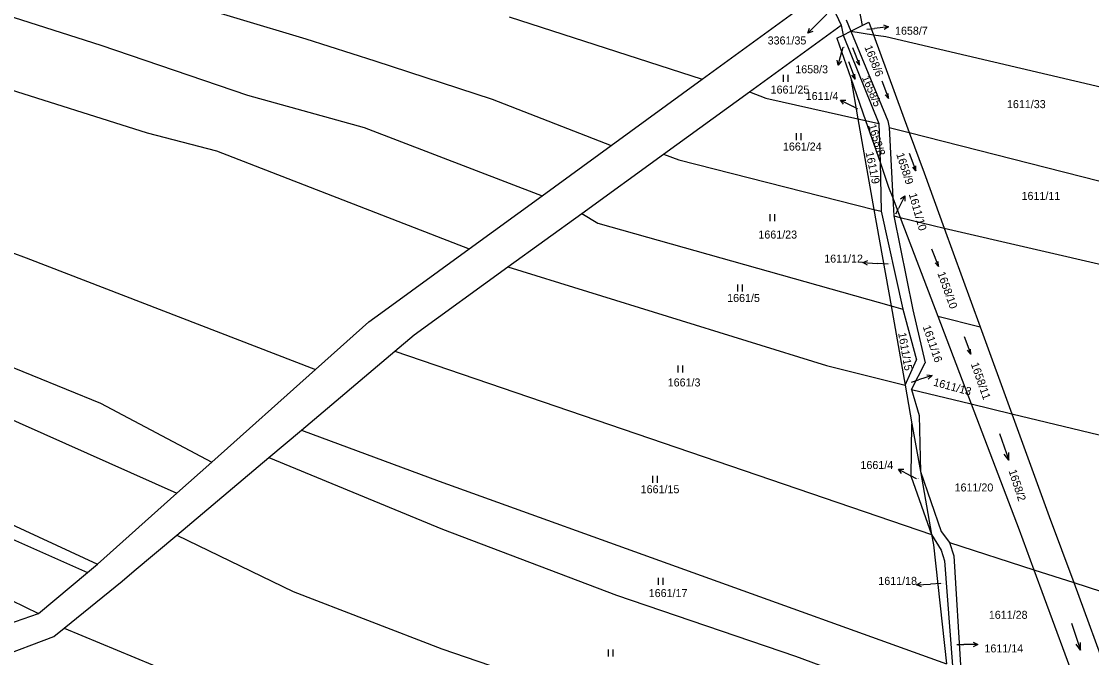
# Model space of a CAD drawing. Extents: x -763205 to -760228, y -1155311 to -1152844.
# Drawn here: x -761366.2 to -761138.9, y -1155010.6 to -1154875.5 of the extents above; entities that cross this region are included whole.
import ezdxf

# ---------------------------------------------------------------- set-up
doc = ezdxf.new("R2010")
doc.units = 0
for name, color, linetype in [('Vrstva 1', 7, 'Continuous'), ('Vrstva 16', 7, 'Continuous'), ('Vrstva 18', 7, 'Continuous'), ('Vrstva 25', 7, 'Continuous'), ('Vrstva 6', 7, 'Continuous')]:
    doc.layers.add(name, color=color, linetype=linetype)

msp = doc.modelspace()

# ---------------------------------------------------------------- linework, layer by layer
at = {"layer": 'Vrstva 1'}
for p, q in [((-761195.65, -1154868.82), (-761192.1, -1154876.29)), ((-761221.63, -1154887.74), (-761201.41, -1154873.02)), ((-761188.31, -1154873.02), (-761187.68, -1154876.37)), ((-761211.62, -1154890.45), (-761192.1, -1154876.29)), ((-761192.1, -1154876.29), (-761191.73, -1154878.38)), ((-761191.73, -1154878.38), (-761190.05, -1154877.55)), ((-761190.05, -1154877.55), (-761187.68, -1154876.37)), ((-761187.68, -1154876.37), (-761186.24, -1154875.66)), ((-761186.24, -1154875.66), (-761185.28, -1154878.29)), ((-761193.07, -1154879.04), (-761191.73, -1154878.38)), ((-761193.07, -1154879.04), (-761190.11, -1154887.54)), ((-761185.28, -1154878.29), (-761177.67, -1154899.07)), ((-761241, -1154901.84), (-761221.63, -1154887.74)), ((-761190.11, -1154887.54), (-761188.58, -1154896.17)), ((-761190.11, -1154887.54), (-761186.97, -1154896.53)), ((-761229.89, -1154903.7), (-761211.62, -1154890.45)), ((-761188.58, -1154896.17), (-761185.17, -1154915.39)), ((-761186.97, -1154896.53), (-761183.88, -1154905.38)), ((-761177.67, -1154899.07), (-761174.53, -1154907.64)), ((-761255.66, -1154912.52), (-761241, -1154901.84)), ((-761247.22, -1154916.27), (-761229.89, -1154903.7)), ((-761183.88, -1154905.38), (-761182.05, -1154910.64)), ((-761174.53, -1154907.64), (-761170.25, -1154919.38)), ((-761182.05, -1154910.64), (-761181.17, -1154912.96)), ((-761271.12, -1154923.77), (-761255.66, -1154912.52)), ((-761181.17, -1154912.96), (-761179.59, -1154917.1)), ((-761262.89, -1154927.63), (-761247.22, -1154916.27)), ((-761185.17, -1154915.39), (-761181.53, -1154935.91)), ((-761179.59, -1154917.1), (-761171.61, -1154938.06)), ((-761170.25, -1154919.38), (-761162.6, -1154940.36)), ((-761289.89, -1154937.43), (-761271.12, -1154923.77)), ((-761282.79, -1154942.07), (-761262.89, -1154927.63)), ((-761181.53, -1154935.91), (-761178.55, -1154952.76)), ((-761292.41, -1154939.27), (-761289.89, -1154937.43)), ((-761171.61, -1154938.06), (-761164.52, -1154956.7)), ((-761301.81, -1154947.66), (-761292.41, -1154939.27)), ((-761162.6, -1154940.36), (-761155.88, -1154958.78)), ((-761286.9, -1154945.53), (-761282.79, -1154942.07)), ((-761306.76, -1154962.27), (-761286.9, -1154945.53)), ((-761303.78, -1154949.42), (-761301.81, -1154947.66)), ((-761325.77, -1154969.06), (-761303.78, -1154949.42)), ((-761178.55, -1154952.76), (-761177.1, -1154960.95)), ((-761164.52, -1154956.7), (-761154.35, -1154983.45)), ((-761155.88, -1154958.78), (-761147.93, -1154980.59)), ((-761177.1, -1154960.95), (-761175.3, -1154971.09)), ((-761313.66, -1154968.08), (-761306.76, -1154962.27)), ((-761333.24, -1154984.59), (-761313.66, -1154968.08)), ((-761333.18, -1154975.68), (-761325.77, -1154969.06)), ((-761175.3, -1154971.09), (-761172.94, -1154984.41)), ((-761387.81, -1154973.33), (-761350.06, -1154990.75)), ((-761350.06, -1154990.75), (-761333.18, -1154975.68)), ((-761147.93, -1154980.59), (-761142.75, -1154994.66)), ((-761342.25, -1154992.18), (-761333.24, -1154984.59)), ((-761172.94, -1154984.41), (-761172.54, -1154986.65)), ((-761154.35, -1154983.45), (-761151.21, -1154991.93)), ((-761172.54, -1154986.65), (-761169.79, -1155011.88)), ((-761352.18, -1154992.53), (-761350.06, -1154990.75)), ((-761362.61, -1155001.24), (-761352.18, -1154992.53)), ((-761344.85, -1154994.37), (-761342.25, -1154992.18)), ((-761151.21, -1154991.93), (-761139.81, -1155022.71)), ((-761357.13, -1155004.33), (-761344.85, -1154994.37)), ((-761142.75, -1154994.66), (-761131.35, -1155025.67)), ((-761370.7, -1155004.05), (-761362.61, -1155001.24)), ((-761359.34, -1155006.12), (-761357.13, -1155004.33)), ((-761380.91, -1155014.27), (-761359.34, -1155006.12))]:
    msp.add_line(p, q, dxfattribs=at)
at = {"layer": 'Vrstva 16'}
for p, q in [((-761193.39, -1154872.07), (-761197.08, -1154875.83)), ((-761199.178, -1154877.974), (-761197.08, -1154875.83)), ((-761186.67, -1154877.14), (-761185.06, -1154876.95)), ((-761182.08, -1154876.601), (-761185.06, -1154876.95)), ((-761192.774, -1154884.791), (-761192.01, -1154881.89)), ((-761191.76, -1154880.95), (-761192.01, -1154881.89)), ((-761192.263, -1154892.169), (-761189.61, -1154893.57)), ((-761188.62, -1154894.09), (-761189.61, -1154893.57)), ((-761178.6, -1154912.506), (-761179.94, -1154915.19)), ((-761180.52, -1154916.35), (-761179.94, -1154915.19)), ((-761187.505, -1154926.701), (-761184.51, -1154926.88)), ((-761182.16, -1154927.02), (-761184.51, -1154926.88)), ((-761177.17, -1154952.11), (-761175.68, -1154951.62)), ((-761172.829, -1154950.686), (-761175.68, -1154951.62)), ((-761179.937, -1154970.532), (-761177.31, -1154971.98)), ((-761176.13, -1154972.63), (-761177.31, -1154971.98)), ((-761176.125, -1154995.145), (-761173.13, -1154994.97)), ((-761170.97, -1154994.84), (-761173.13, -1154994.97)), ((-761167.53, -1155007.78), (-761166.09, -1155007.78)), ((-761163.09, -1155007.781), (-761166.09, -1155007.78))]:
    msp.add_line(p, q, dxfattribs=at)
for points in [[(-761198.121, -1154877.609), (-761199.178, -1154877.974), (-761198.836, -1154876.91)], [(-761183.132, -1154876.221), (-761182.08, -1154876.601), (-761183.015, -1154877.214)], [(-761192.036, -1154883.951), (-761192.774, -1154884.791), (-761193.003, -1154883.697)], [(-761191.612, -1154893.078), (-761192.263, -1154892.169), (-761191.145, -1154892.194)], [(-761179.494, -1154913.177), (-761178.6, -1154912.506), (-761178.599, -1154913.624)], [(-761186.536, -1154927.26), (-761187.505, -1154926.701), (-761186.477, -1154926.261)], [(-761173.935, -1154950.522), (-761172.829, -1154950.686), (-761173.624, -1154951.472)], [(-761179.303, -1154971.452), (-761179.937, -1154970.532), (-761178.82, -1154970.577)], [(-761175.098, -1154995.585), (-761176.125, -1154995.145), (-761175.156, -1154994.587)], [(-761164.09, -1155007.281), (-761163.09, -1155007.781), (-761164.09, -1155008.281)]]:
    msp.add_lwpolyline(points, dxfattribs=at)
at = {"layer": 'Vrstva 25'}
for p, q in [((-761204.36, -1154888.33), (-761204.36, -1154886.83)), ((-761203.36, -1154888.33), (-761203.36, -1154886.83)), ((-761201.6, -1154900.7), (-761201.6, -1154899.2)), ((-761200.6, -1154900.7), (-761200.6, -1154899.2)), ((-761207.23, -1154917.9), (-761207.23, -1154916.4)), ((-761206.23, -1154917.9), (-761206.23, -1154916.4)), ((-761214.07, -1154932.86), (-761214.07, -1154931.36)), ((-761213.07, -1154932.86), (-761213.07, -1154931.36)), ((-761226.74, -1154950.07), (-761226.74, -1154948.57)), ((-761225.74, -1154950.07), (-761225.74, -1154948.57)), ((-761232.14, -1154973.48), (-761232.14, -1154971.98)), ((-761231.14, -1154973.48), (-761231.14, -1154971.98)), ((-761230.9, -1154995.14), (-761230.9, -1154993.64)), ((-761229.9, -1154995.14), (-761229.9, -1154993.64)), ((-761241.56, -1155010.38), (-761241.56, -1155008.88)), ((-761240.56, -1155010.38), (-761240.56, -1155008.88))]:
    msp.add_line(p, q, dxfattribs=at)
for points in [[(-761189.693, -1154881.031), (-761188.267, -1154884.789), (-761188.31, -1154883.731)], [(-761190.605, -1154883.981), (-761189.175, -1154887.739), (-761189.219, -1154886.68)], [(-761188.267, -1154884.789), (-761188.937, -1154883.968)], [(-761189.175, -1154887.739), (-761189.846, -1154886.918)], [(-761183.523, -1154888.111), (-761182.097, -1154891.869), (-761182.14, -1154890.811)], [(-761182.097, -1154891.869), (-761182.767, -1154891.048)], [(-761177.663, -1154903.471), (-761176.237, -1154907.229), (-761176.28, -1154906.171)], [(-761176.237, -1154907.229), (-761176.907, -1154906.408)], [(-761172.913, -1154923.781), (-761171.487, -1154927.539), (-761171.53, -1154926.481)], [(-761171.487, -1154927.539), (-761172.157, -1154926.718)], [(-761166.033, -1154942.381), (-761164.607, -1154946.139), (-761164.65, -1154945.081)], [(-761164.607, -1154946.139), (-761165.277, -1154945.318)], [(-761158.471, -1154962.961), (-761156.529, -1154968.639), (-761156.541, -1154967.057)], [(-761156.529, -1154968.639), (-761157.488, -1154967.381)], [(-761143.211, -1155003.301), (-761141.269, -1155008.979), (-761141.281, -1155007.397)], [(-761141.269, -1155008.979), (-761142.228, -1155007.721)]]:
    msp.add_lwpolyline(points, dxfattribs=at)
at = {"layer": 'Vrstva 6'}
for p, q in [((-761409.17, -1154861.48), (-761349.34, -1154880.53)), ((-761338.23, -1154869.42), (-761305.79, -1154879.19)), ((-761424.84, -1154872.1), (-761339.52, -1154899.15)), ((-761262.67, -1154874.51), (-761221.63, -1154887.74)), ((-761191.05, -1154875.12), (-761190.05, -1154877.55)), ((-761190.05, -1154877.55), (-761182.24, -1154896.56)), ((-761190.05, -1154877.55), (-761185.28, -1154878.29)), ((-761305.79, -1154879.19), (-761291.13, -1154883.83)), ((-761191.73, -1154878.38), (-761184.1, -1154897.18)), ((-761185.28, -1154878.29), (-761182.62, -1154878.7)), ((-761182.62, -1154878.7), (-761136.75, -1154889.41)), ((-761349.34, -1154880.53), (-761318.18, -1154891.13)), ((-761291.13, -1154883.83), (-761266.22, -1154891.99)), ((-761318.18, -1154891.13), (-761293.46, -1154897.97)), ((-761211.62, -1154890.45), (-761208.12, -1154891.75)), ((-761266.22, -1154891.99), (-761241, -1154901.84)), ((-761208.12, -1154891.75), (-761188.58, -1154896.17)), ((-761443.1, -1154897.33), (-761365.22, -1154925.67)), ((-761293.46, -1154897.97), (-761255.66, -1154912.52)), ((-761188.58, -1154896.17), (-761186.97, -1154896.53)), ((-761186.97, -1154896.53), (-761184.1, -1154897.18)), ((-761184.1, -1154897.18), (-761183.88, -1154905.38)), ((-761182.24, -1154896.56), (-761181.94, -1154897.98)), ((-761181.94, -1154897.98), (-761177.67, -1154899.07)), ((-761181.94, -1154897.98), (-761181.17, -1154912.96)), ((-761339.52, -1154899.15), (-761324.8, -1154902.99)), ((-761177.67, -1154899.07), (-761122.76, -1154913.05)), ((-761324.8, -1154902.99), (-761271.12, -1154923.77)), ((-761229.89, -1154903.7), (-761226.62, -1154904.9)), ((-761226.62, -1154904.9), (-761185.17, -1154915.39)), ((-761183.88, -1154905.38), (-761183.61, -1154915.79)), ((-761181.17, -1154912.96), (-761180.97, -1154916.76)), ((-761247.22, -1154916.27), (-761243.84, -1154918.3)), ((-761185.17, -1154915.39), (-761183.61, -1154915.79)), ((-761183.61, -1154915.79), (-761179.02, -1154936.62)), ((-761243.84, -1154918.3), (-761181.53, -1154935.91)), ((-761180.97, -1154916.76), (-761179.59, -1154917.1)), ((-761180.97, -1154916.76), (-761176.93, -1154936.71)), ((-761179.59, -1154917.1), (-761170.25, -1154919.38)), ((-761170.25, -1154919.38), (-761125.49, -1154929.76)), ((-761365.22, -1154925.67), (-761303.78, -1154949.42)), ((-761262.89, -1154927.63), (-761195.26, -1154948.55)), ((-761405.99, -1154933.61), (-761349.41, -1154956.53)), ((-761181.53, -1154935.91), (-761179.02, -1154936.62)), ((-761179.02, -1154936.62), (-761176.13, -1154947.36)), ((-761176.93, -1154936.71), (-761174.29, -1154947.95)), ((-761171.61, -1154938.06), (-761162.6, -1154940.36)), ((-761409.73, -1154941.52), (-761333.18, -1154975.68)), ((-761286.9, -1154945.53), (-761172.94, -1154984.41)), ((-761178.55, -1154952.76), (-761176.13, -1154947.36)), ((-761177.18, -1154953.65), (-761174.29, -1154947.95)), ((-761195.26, -1154948.55), (-761178.55, -1154952.76)), ((-761177.18, -1154953.65), (-761175.53, -1154959.19)), ((-761177.18, -1154953.65), (-761164.52, -1154956.7)), ((-761349.41, -1154956.53), (-761325.77, -1154969.06)), ((-761164.52, -1154956.7), (-761155.88, -1154958.78)), ((-761175.53, -1154959.19), (-761175.3, -1154971.09)), ((-761155.88, -1154958.78), (-761121.29, -1154967.13)), ((-761177.24, -1154972.22), (-761177.1, -1154960.95)), ((-761417.7, -1154963.38), (-761352.18, -1154992.53)), ((-761306.76, -1154962.27), (-761277.5, -1154973.14)), ((-761313.66, -1154968.08), (-761276.81, -1154983.3)), ((-761277.5, -1154973.14), (-761169.79, -1155011.88)), ((-761177.24, -1154972.22), (-761172.94, -1154984.41)), ((-761175.3, -1154971.09), (-761170.88, -1154983.8)), ((-761333.24, -1154984.59), (-761308.48, -1154996.56)), ((-761276.81, -1154983.3), (-761239.81, -1154997.3)), ((-761172.94, -1154984.41), (-761170.88, -1154987.76)), ((-761170.88, -1154983.8), (-761169.11, -1154986.16)), ((-761169.11, -1154986.16), (-761151.21, -1154991.93)), ((-761169.11, -1154986.16), (-761168.17, -1154988.95)), ((-761170.88, -1154987.76), (-761170.15, -1154990.02)), ((-761168.17, -1154988.95), (-761166.71, -1155013.3)), ((-761383.71, -1154990.87), (-761362.61, -1155001.24)), ((-761170.15, -1154990.02), (-761168.47, -1155012.36)), ((-761151.21, -1154991.93), (-761142.75, -1154994.66)), ((-761142.75, -1154994.66), (-761108.27, -1155005.79)), ((-761308.48, -1154996.56), (-761276.94, -1155008.72)), ((-761239.81, -1154997.3), (-761201.82, -1155010.26)), ((-761357.13, -1155004.33), (-761334.64, -1155013.67)), ((-761276.94, -1155008.72), (-761188.63, -1155038.79)), ((-761201.82, -1155010.26), (-761168.58, -1155022.51))]:
    msp.add_line(p, q, dxfattribs=at)

# ---------------------------------------------------------------- texts
at = {"layer": 'Vrstva 16'}
for s, p in [('1658/7', (-761180.687, -1154878.3)), ('3361/35', (-761207.742, -1154880.37)), ('1658/3', (-761201.878, -1154886.49)), ('1611/4', (-761199.655, -1154892.17)), ('1611/12', (-761195.725, -1154926.7)), ('1661/4', (-761188.031, -1154970.53)), ('1611/18', (-761184.237, -1154995.14)), ('1611/14', (-761161.697, -1155009.48))]:
    msp.add_text(s, height=1.7, dxfattribs=at).set_placement(p)
for s, rotation, p in [('1611/10', 285.84864, (-761177.793, -1154912.168)), ('1611/13', 344.806, (-761172.677, -1154952.793))]:
    msp.add_text(s, height=1.7, rotation=rotation, dxfattribs=at).set_placement(p)
at = {"layer": 'Vrstva 18'}
for s, height, p in [('1658/7', 0.1, (-761186.647, -1154877.14)), ('1658/3', 0.1, (-761191.737, -1154880.95)), ('1661/25', 1.7, (-761207.107, -1154890.8)), ('1611/33', 1.7, (-761156.917, -1154893.89)), ('1611/4', 0.1, (-761188.597, -1154894.09)), ('1661/24', 1.7, (-761204.497, -1154902.9)), ('1611/11', 1.7, (-761153.817, -1154913.38)), ('1611/10', 0.1, (-761180.497, -1154916.35)), ('1661/23', 1.7, (-761209.707, -1154921.59)), ('1611/12', 0.1, (-761182.137, -1154927.02)), ('1661/5', 1.7, (-761216.337, -1154935.06)), ('1661/3', 1.7, (-761228.967, -1154953)), ('1611/13', 0.1, (-761177.147, -1154952.11)), ('1661/4', 0.1, (-761176.107, -1154972.63)), ('1661/15', 1.7, (-761234.707, -1154975.68)), ('1611/20', 1.7, (-761168.037, -1154975.3)), ('1661/17', 1.7, (-761232.997, -1154997.73)), ('1611/18', 0.1, (-761170.947, -1154994.84)), ('1611/28', 1.7, (-761160.767, -1155002.35)), ('1611/14', 0.1, (-761167.507, -1155007.78))]:
    msp.add_text(s, height=height, dxfattribs=at).set_placement(p)
for s, rotation, p in [('1658/6', 291.52092, (-761187.236, -1154880.915)), ('1658/5', 293.06791, (-761187.757, -1154887.382)), ('1658/8', 287.45292, (-761186.401, -1154897.551)), ('1611/9', 281.78064, (-761186.95, -1154903.314)), ('1658/9', 288.08318, (-761180.468, -1154903.663)), ('1658/10', 289.85935, (-761171.737, -1154928.959)), ('1611/16', 288.88532, (-761174.843, -1154940.302)), ('1611/15', 279.83259, (-761180.033, -1154941.667)), ('1658/11', 289.28639, (-761164.62, -1154948.221)), ('1658/2', 288.08318, (-761156.598, -1154970.933))]:
    msp.add_text(s, height=1.7, rotation=rotation, dxfattribs=at).set_placement(p)

doc.saveas('drawing.dxf')
